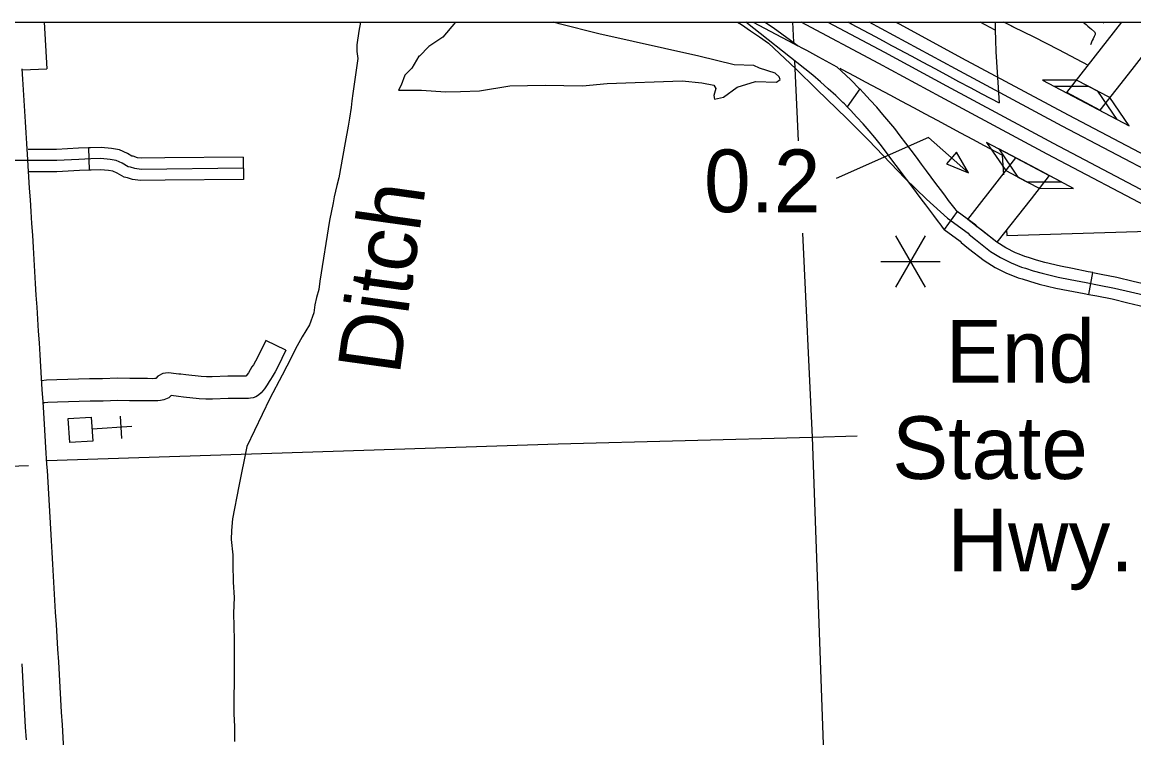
# Model space of a CAD drawing. Extents: x -117616 to 64730, y 54117 to 789866.
# Drawn here: x 62435.1 to 62585, y 55218.5 to 55314.9 of the extents above; entities that cross this region are included whole.
import ezdxf

# ---------------------------------------------------------------- set-up
doc = ezdxf.new("R2010")
doc.units = 0
for name, color, linetype in [('Level 10', 7, 'Continuous'), ('Level 19', 7, 'Continuous'), ('Level 31', 7, 'Continuous'), ('Level 32', 7, 'Continuous'), ('Level 33', 7, 'Continuous'), ('Level 34', 7, 'Continuous'), ('Level 35', 7, 'Continuous'), ('Level 40', 7, 'Continuous'), ('Level 41', 7, 'Continuous'), ('Level 42', 7, 'Continuous'), ('Level 45', 7, 'Continuous'), ('Level 46', 7, 'Continuous'), ('Level 48', 7, 'Continuous'), ('Level 5', 7, 'Continuous'), ('Level 57', 7, 'Continuous'), ('Level 6', 7, 'Continuous'), ('R_No Plot', 7, 'Continuous')]:
    doc.layers.add(name, color=color, linetype=linetype)

msp = doc.modelspace()

# ---------------------------------------------------------------- linework, layer by layer
at = {"layer": 'Level 10'}
for p, q in [((62575.96, 55305.45), (62583.37, 55314.94)), ((62583.37, 55314.94), (62589.63, 55314.94)), ((62588.03, 55312.78), (62584.75, 55308.58)), ((62435.19, 55307.25), (62435.11, 55308.67)), ((62584.75, 55308.58), (62580.44, 55303.07)), ((62435.28, 55305.83), (62435.19, 55307.25)), ((62435.37, 55304.39), (62435.28, 55305.83)), ((62580.44, 55303.07), (62575.96, 55305.45)), ((62435.46, 55302.95), (62435.37, 55304.39)), ((62435.56, 55301.5), (62435.46, 55302.95)), ((62435.65, 55300.04), (62435.56, 55301.5)), ((62435.74, 55298.58), (62435.65, 55300.04)), ((62435.83, 55297.1), (62435.74, 55298.58)), ((62435.87, 55296.44), (62435.83, 55297.1)), ((62435.92, 55295.6), (62435.87, 55296.44)), ((62436, 55294.09), (62435.92, 55295.6)), ((62436.1, 55292.57), (62436, 55294.09)), ((62436.21, 55291.01), (62436.1, 55292.57)), ((62436.31, 55289.42), (62436.21, 55291.01)), ((62436.42, 55287.82), (62436.31, 55289.42)), ((62436.52, 55286.21), (62436.42, 55287.82)), ((62436.62, 55284.58), (62436.52, 55286.21)), ((62436.71, 55282.97), (62436.62, 55284.58)), ((62436.81, 55281.34), (62436.71, 55282.97)), ((62436.91, 55279.73), (62436.81, 55281.34)), ((62437, 55278.12), (62436.91, 55279.73)), ((62437.11, 55276.52), (62437, 55278.12)), ((62437.21, 55274.91), (62437.11, 55276.52)), ((62437.32, 55273.31), (62437.21, 55274.91)), ((62437.42, 55271.71), (62437.32, 55273.31)), ((62437.52, 55270.12), (62437.42, 55271.71)), ((62437.62, 55268.54), (62437.52, 55270.12)), ((62437.72, 55266.97), (62437.62, 55268.54)), ((62437.82, 55265.42), (62437.72, 55266.97)), ((62437.93, 55263.74), (62437.82, 55265.42)), ((62438.02, 55262.3), (62437.93, 55263.74)), ((62438.12, 55260.74), (62438.02, 55262.3)), ((62438.22, 55259.18), (62438.12, 55260.74)), ((62438.31, 55257.62), (62438.22, 55259.18)), ((62438.45, 55255.34), (62438.31, 55257.62)), ((62438.5, 55254.5), (62438.45, 55255.34)), ((62438.6, 55252.94), (62438.5, 55254.5)), ((62438.69, 55251.37), (62438.6, 55252.94)), ((62438.79, 55249.8), (62438.69, 55251.37)), ((62438.88, 55248.23), (62438.79, 55249.8)), ((62438.97, 55246.65), (62438.88, 55248.23)), ((62439.06, 55245.06), (62438.97, 55246.65)), ((62439.16, 55243.47), (62439.06, 55245.06)), ((62439.25, 55241.87), (62439.16, 55243.47)), ((62439.35, 55240.26), (62439.25, 55241.87)), ((62439.44, 55238.65), (62439.35, 55240.26)), ((62439.53, 55237.03), (62439.44, 55238.65)), ((62439.62, 55235.41), (62439.53, 55237.03)), ((62439.72, 55233.76), (62439.62, 55235.41)), ((62439.82, 55232.1), (62439.72, 55233.76)), ((62439.93, 55230.42), (62439.82, 55232.1)), ((62440.03, 55228.72), (62439.93, 55230.42)), ((62440.13, 55227.01), (62440.03, 55228.72)), ((62435.04, 55228.42), (62435.13, 55226.73)), ((62435.13, 55226.73), (62435.23, 55225.03)), ((62440.22, 55225.31), (62440.13, 55227.01)), ((62435.23, 55225.03), (62435.33, 55223.33)), ((62440.32, 55223.62), (62440.22, 55225.31)), ((62435.33, 55223.33), (62435.43, 55221.62)), ((62440.42, 55221.92), (62440.32, 55223.62)), ((62435.43, 55221.62), (62435.53, 55219.91)), ((62440.53, 55220.22), (62440.42, 55221.92)), ((62435.53, 55219.91), (62435.64, 55218.21)), ((62440.63, 55218.52), (62440.53, 55220.22)), ((62440.74, 55216.81), (62440.63, 55218.52))]:
    msp.add_line(p, q, dxfattribs=at)
for points in [[(62566.54, 55285.27), (62562.6, 55288.35), (62567.21, 55294.23), (62569.09, 55296.64), (62573.57, 55294.26)], [(62573.57, 55294.26), (62571.15, 55291.15), (62566.54, 55285.27)]]:
    msp.add_lwpolyline(points, dxfattribs=at)
at = {"layer": 'Level 19'}
for p, q in [((62550.6, 55309.38), (62540.14, 55314.94)), ((62540.14, 55314.94), (62543.76, 55314.94)), ((62543.76, 55314.94), (62551.4, 55310.88)), ((62552.63, 55313.17), (62549.3, 55314.94)), ((62549.3, 55314.94), (62552.93, 55314.94)), ((62552.93, 55314.94), (62553.44, 55314.67)), ((62553.44, 55314.67), (62561.78, 55310.14)), ((62560.98, 55308.64), (62552.63, 55313.17)), ((62551.4, 55310.88), (62559.74, 55306.35)), ((62561.78, 55310.14), (62576.16, 55302.44)), ((62558.94, 55304.86), (62550.6, 55309.38)), ((62575.36, 55300.93), (62560.98, 55308.64)), ((62559.74, 55306.35), (62574.14, 55298.64)), ((62573.34, 55297.14), (62558.94, 55304.86)), ((62576.16, 55302.44), (62594.33, 55292.86)), ((62593.52, 55291.37), (62575.36, 55300.93)), ((62574.14, 55298.64), (62592.28, 55289.08)), ((62591.47, 55287.59), (62573.34, 55297.14))]:
    msp.add_line(p, q, dxfattribs=at)
at = {"layer": 'Level 31'}
for p, q in [((62540.62, 55308.67), (62532.69, 55314.94)), ((62532.69, 55314.94), (62533.69, 55314.94)), ((62533.69, 55314.94), (62535.99, 55313.74)), ((62566.33, 55313.89), (62564.3, 55314.94)), ((62564.3, 55314.94), (62566.3, 55314.94)), ((62566.3, 55314.94), (62566.33, 55313.89)), ((62535.99, 55313.74), (62539.11, 55312.08)), ((62539.11, 55312.08), (62540.87, 55311.15)), ((62540.87, 55311.15), (62542.48, 55310.28)), ((62542.48, 55310.28), (62544.97, 55308.94)), ((62541.71, 55307.79), (62540.62, 55308.67)), ((62544.97, 55308.94), (62546.84, 55307.16)), ((62542.77, 55306.89), (62541.71, 55307.79)), ((62543.8, 55305.98), (62542.77, 55306.89)), ((62546.84, 55307.16), (62547.05, 55306.95)), ((62547.05, 55306.95), (62547.81, 55306.2)), ((62544.81, 55305.06), (62543.8, 55305.98)), ((62545.78, 55304.13), (62544.81, 55305.06)), ((62548.05, 55305.95), (62546.35, 55303.55)), ((62547.81, 55306.2), (62547.93, 55306.07)), ((62547.93, 55306.07), (62548.05, 55305.95)), ((62545.98, 55303.95), (62545.78, 55304.13)), ((62546.35, 55303.55), (62545.98, 55303.95)), ((62561.2, 55289.42), (62559.43, 55287.01)), ((62578.93, 55278.24), (62579.49, 55281.19)), ((62578.93, 55278.24), (62578.93, 55278.24))]:
    msp.add_line(p, q, dxfattribs=at)
for points in [[(62531.58, 55314.94), (62532.11, 55314.61), (62533.33, 55313.8), (62534.54, 55312.97), (62535.73, 55312.11)], [(62567.58, 55314.94), (62568.73, 55314.34), (62571.52, 55312.97), (62574.84, 55311.28), (62578.83, 55309.13)], [(62535.73, 55312.11), (62539.44, 55308.67), (62542.28, 55305.89), (62546.29, 55301.95), (62549.22, 55299.02), (62554.17, 55293.87), (62557.04, 55291.07), (62559.9, 55288.52), (62562.66, 55286.49), (62562.8, 55286.31), (62563.65, 55285.63)], [(62561.2, 55289.42), (62560.92, 55289.76), (62560.54, 55290.24), (62560.03, 55290.92), (62559.5, 55291.64), (62558.93, 55292.4), (62558.32, 55293.21), (62557.7, 55294.04), (62557.04, 55294.91), (62556.37, 55295.8), (62555.68, 55296.73), (62554.97, 55297.68), (62554.25, 55298.65), (62553.51, 55299.62), (62552.76, 55300.59), (62551.99, 55301.56), (62551.18, 55302.52), (62550.33, 55303.48), (62549.46, 55304.44), (62548.57, 55305.41), (62548.05, 55305.95)], [(62559.43, 55287.01), (62559.01, 55287.57), (62558.54, 55288.19), (62558.04, 55288.87), (62557.51, 55289.59), (62556.94, 55290.34), (62556.34, 55291.14), (62555.71, 55291.98), (62555.06, 55292.85), (62554.37, 55293.76), (62553.69, 55294.68), (62552.98, 55295.63), (62552.26, 55296.58), (62551.54, 55297.54), (62550.82, 55298.48), (62550.08, 55299.4), (62549.31, 55300.31), (62548.51, 55301.23), (62547.66, 55302.16), (62546.8, 55303.09), (62546.35, 55303.55)], [(62569.54, 55283.67), (62569.07, 55283.86), (62567.75, 55284.52), (62566.54, 55285.27), (62564.58, 55286.8), (62563.88, 55287.36), (62563.72, 55287.57), (62561.2, 55289.42)], [(62559.43, 55287.01), (62561.6, 55285.41), (62561.72, 55285.25), (62562.71, 55284.45), (62564.82, 55282.8), (62566.29, 55281.89), (62567.84, 55281.12), (62568.43, 55280.89)], [(62563.65, 55285.63), (62565.68, 55284.03), (62567.02, 55283.21), (62568.46, 55282.49), (62569.85, 55281.93), (62570.39, 55281.8), (62571.41, 55281.44), (62572.64, 55281.09), (62574.82, 55280.56), (62576.44, 55280.24), (62578.58, 55279.83), (62580.31, 55279.5), (62582.42, 55279.1), (62584.55, 55278.59), (62586.89, 55278.04)], [(62579.49, 55281.19), (62578.86, 55281.31), (62576.72, 55281.72), (62575.14, 55282.03), (62573.02, 55282.54), (62571.87, 55282.87), (62570.82, 55283.24), (62570.31, 55283.36), (62569.54, 55283.67)], [(62579.49, 55281.19), (62580.59, 55280.98), (62582.73, 55280.56), (62584.9, 55280.05), (62587.26, 55279.49), (62589.64, 55278.83), (62589.89, 55278.76)], [(62568.43, 55280.89), (62569.39, 55280.5), (62569.97, 55280.36), (62570.96, 55280.01), (62572.26, 55279.64), (62574.5, 55279.1), (62576.15, 55278.77), (62578.3, 55278.36), (62578.93, 55278.24)], [(62578.93, 55278.24), (62580.03, 55278.03), (62582.1, 55277.63), (62584.2, 55277.13), (62586.51, 55276.59), (62588.84, 55275.95), (62589.08, 55275.88)]]:
    msp.add_lwpolyline(points, dxfattribs=at)
at = {"layer": 'Level 32'}
msp.add_lwpolyline([(62406.52, 55254.14), (62409.69, 55254.26), (62435.95, 55255.19)], dxfattribs=at)
at = {"layer": 'Level 33'}
for points in [[(62539.6, 55311.82), (62538.73, 55312.47), (62537.55, 55313.33), (62536.36, 55314.17), (62535.22, 55314.94)], [(62568.73, 55314.34), (62567.76, 55314.8), (62567.46, 55314.94)]]:
    msp.add_lwpolyline(points, dxfattribs=at)
at = {"layer": 'Level 34'}
msp.add_lwpolyline([(62578.19, 55314.94), (62578.59, 55314.64), (62578.82, 55314.4), (62579.06, 55314.17), (62579.3, 55313.99), (62579.7, 55313.63), (62579.75, 55313.57), (62579.79, 55313.51), (62579.8, 55313.4), (62579.78, 55313.28), (62579.68, 55313.02), (62579.51, 55312.69), (62579.37, 55312.48), (62579.15, 55311.91)], dxfattribs=at)
at = {"layer": 'Level 35'}
for points in [[(62480.72, 55314.94), (62480.49, 55313.75), (62480.24, 55311.87), (62480.24, 55311.01), (62480.37, 55310.07), (62479.71, 55305.35), (62479.54, 55304.33), (62479.45, 55303.43), (62479.23, 55302), (62479.07, 55300.91), (62478.67, 55298.72), (62478.35, 55296.99), (62477.79, 55293.97), (62477.54, 55292.93), (62477.19, 55291.39), (62477.03, 55290.6), (62476.53, 55288.21), (62475.24, 55280.01), (62475.12, 55278.91), (62474.8, 55277.84), (62474.58, 55276.83), (62474.43, 55275.76), (62473.86, 55274.13), (62472.84, 55272.53), (62472.2, 55271.29), (62470.81, 55268.56), (62470.15, 55267.37), (62468.52, 55264.22), (62465.41, 55257.73), (62464.32, 55252.41), (62463.48, 55247.99), (62463.33, 55246.43), (62463.29, 55245.21), (62463.52, 55243.12), (62463.52, 55241.89), (62463.56, 55239.44), (62463.68, 55237.39), (62463.6, 55235.28), (62463.68, 55231.67), (62463.68, 55228.68), (62463.69, 55227.51), (62463.68, 55225.43), (62463.64, 55224.5), (62463.65, 55223.28), (62463.64, 55221.72), (62463.72, 55220), (62463.73, 55217.97)], [(62493.54, 55314.94), (62491.83, 55312.93), (62489.96, 55311.65), (62488.68, 55310.37), (62488.59, 55310.37), (62487.65, 55308.75), (62486.72, 55307.81), (62486.21, 55306.45), (62485.87, 55305.77), (62488.93, 55305.77), (62492.18, 55305.54), (62494.22, 55305.6), (62496.77, 55305.68), (62500.86, 55306.36), (62505.63, 55306.45), (62510.66, 55306.36), (62513.98, 55306.7), (62524.12, 55307.04), (62526.76, 55306.79), (62528.38, 55306.45), (62528.64, 55306.02), (62528.38, 55305.08), (62528.47, 55304.57), (62529.66, 55304.83), (62531.53, 55306.19), (62534, 55306.96), (62536.82, 55306.87), (62537.33, 55307.22), (62537.16, 55307.56), (62536.65, 55308.07), (62534.52, 55308.75), (62533.75, 55309.09), (62531.11, 55309.18), (62526.34, 55310.37), (62512.87, 55313.36), (62507.51, 55314.72), (62506.8, 55314.94)]]:
    msp.add_lwpolyline(points, dxfattribs=at)
at = {"layer": 'Level 40'}
msp.add_line((62580.92, 55314.94), (62580.82, 55314.79), dxfattribs=at)
at = {"layer": 'Level 42'}
for p, q in [((62577.28, 55307.14), (62572.67, 55307.13)), ((62572.67, 55307.13), (62577.71, 55304.48)), ((62580.15, 55305.63), (62577.28, 55307.14)), ((62578.91, 55306.29), (62574.29, 55306.28)), ((62574.29, 55306.28), (62579.34, 55303.62)), ((62581.78, 55304.78), (62578.91, 55306.29)), ((62582.76, 55301.82), (62580.15, 55305.63)), ((62577.71, 55304.48), (62582.76, 55301.82)), ((62579.34, 55303.62), (62584.38, 55300.96)), ((62584.38, 55300.96), (62581.78, 55304.78)), ((62570.19, 55296.08), (62565.16, 55298.74)), ((62565.16, 55298.74), (62567.75, 55294.93)), ((62571.82, 55295.21), (62566.79, 55297.88)), ((62566.79, 55297.88), (62569.38, 55294.06)), ((62575.23, 55293.41), (62570.19, 55296.08)), ((62567.75, 55294.93), (62570.62, 55293.41)), ((62576.86, 55292.54), (62571.82, 55295.21)), ((62569.38, 55294.06), (62572.25, 55292.55)), ((62570.62, 55293.41), (62575.23, 55293.41)), ((62572.25, 55292.55), (62576.86, 55292.54))]:
    msp.add_line(p, q, dxfattribs=at)
at = {"layer": 'Level 45'}
for p, q in [((62444.03, 55297.99), (62444.13, 55294.99)), ((62464.91, 55296.75), (62464.95, 55293.75))]:
    msp.add_line(p, q, dxfattribs=at)
for points in [[(62444.03, 55297.99), (62442.7, 55297.94), (62439.72, 55297.79), (62437.44, 55297.79), (62435.92, 55297.79)], [(62454.36, 55296.64), (62451.22, 55296.6), (62450.64, 55296.67), (62450.05, 55296.87), (62449.9, 55296.89), (62449.29, 55297.26), (62448.22, 55297.73), (62447.15, 55297.93), (62445.74, 55298.05), (62444.31, 55298), (62444.03, 55297.99)], [(62464.93, 55295.25), (62451.13, 55295.1), (62450.31, 55295.2), (62449.69, 55295.41), (62449.38, 55295.46), (62448.6, 55295.93), (62447.77, 55296.29), (62446.95, 55296.44), (62445.71, 55296.55), (62444.36, 55296.5), (62442.76, 55296.44), (62439.76, 55296.29), (62437.44, 55296.29), (62433.37, 55296.29)], [(62464.91, 55296.75), (62454.36, 55296.64)], [(62444.13, 55294.99), (62442.82, 55294.95), (62439.8, 55294.79), (62437.44, 55294.79), (62435.92, 55294.79)], [(62454.39, 55293.64), (62451.05, 55293.6), (62449.97, 55293.73), (62449.32, 55293.95), (62448.85, 55294.03), (62447.91, 55294.59), (62447.33, 55294.85), (62446.75, 55294.96), (62445.67, 55295.05), (62444.42, 55295), (62444.13, 55294.99)], [(62464.95, 55293.75), (62454.39, 55293.64)]]:
    msp.add_lwpolyline(points, dxfattribs=at)
at = {"layer": 'Level 46'}
for points in [[(62470.64, 55270.73), (62467.94, 55272.03), (62466.88, 55269.82), (62466.57, 55269.23), (62466.29, 55268.75), (62466.09, 55268.46), (62465.84, 55268.08), (62465.61, 55267.68), (62465.33, 55267.28), (62465.27, 55267.21), (62465.13, 55267.22), (62464.48, 55267.23), (62462.83, 55267.23), (62460.71, 55267.13), (62459.96, 55267.13), (62459.22, 55267.17), (62457.19, 55267.39), (62456.52, 55267.47), (62456.22, 55267.5), (62455.88, 55267.54), (62455.49, 55267.59), (62455.19, 55267.63), (62454.78, 55267.65), (62454.07, 55267.58), (62453.4, 55267.22), (62453.15, 55266.9), (62453.12, 55266.9), (62452.98, 55266.89), (62452.62, 55266.88), (62452.02, 55266.89), (62449.6, 55266.9), (62447.99, 55266.95), (62445.89, 55266.86)], [(62470.64, 55270.73), (62469.56, 55268.48), (62469.2, 55267.79), (62468.82, 55267.13), (62468.57, 55266.77), (62468.4, 55266.51), (62468.13, 55266.06), (62467.76, 55265.52), (62467.35, 55264.98), (62466.98, 55264.68), (62466.63, 55264.45), (62466.24, 55264.31), (62465.91, 55264.24), (62465.64, 55264.22), (62465.37, 55264.21), (62465.06, 55264.22), (62464.46, 55264.23), (62462.9, 55264.23), (62460.79, 55264.13), (62459.87, 55264.13), (62458.97, 55264.18), (62456.86, 55264.41), (62456.19, 55264.48), (62455.87, 55264.52), (62455.5, 55264.57), (62455.2, 55264.6), (62454.86, 55264.29), (62454.2, 55264.05), (62453.75, 55263.96), (62453.41, 55263.91), (62453.08, 55263.89), (62452.63, 55263.88), (62451.99, 55263.89), (62449.56, 55263.9), (62448.01, 55263.94), (62446.01, 55263.87)], [(62445.93, 55266.87), (62444.2, 55266.85), (62439.79, 55266.71), (62438.38, 55266.67), (62437.69, 55266.6)], [(62445.97, 55263.87), (62444.27, 55263.85), (62439.89, 55263.72), (62438.58, 55263.67), (62438.05, 55263.62), (62437.89, 55263.51)]]:
    msp.add_lwpolyline(points, dxfattribs=at)
at = {"layer": 'Level 48'}
for p, q in [((62556.87, 55286.15), (62552.87, 55279.22)), ((62552.87, 55286.15), (62556.87, 55279.22)), ((62550.87, 55282.68), (62558.87, 55282.68))]:
    msp.add_line(p, q, dxfattribs=at)
msp.add_lwpolyline([(62562.71, 55294.62), (62557.34, 55299.42), (62544.88, 55293.85)], dxfattribs=at)
msp.add_lwpolyline([(62561.08, 55297.4), (62559.74, 55295.87), (62562.71, 55294.62)], close=True, dxfattribs=at)
at = {"layer": 'Level 5'}
for points in [[(62538.97, 55314.94), (62539.1, 55312.23)], [(62539.23, 55309.69), (62539.74, 55298.97)], [(62540.33, 55286.48), (62541.65, 55258.99)], [(62438.42, 55255.83), (62507.38, 55258.1), (62541.65, 55258.99)], [(62541.65, 55258.99), (62547.68, 55259.17)], [(62541.65, 55258.99), (62543.14, 55216.35)]]:
    msp.add_lwpolyline(points, dxfattribs=at)
at = {"layer": 'Level 57'}
for p, q in [((62448.32, 55261.83), (62448.51, 55258.84)), ((62449.91, 55260.43), (62444.54, 55260.09))]:
    msp.add_line(p, q, dxfattribs=at)
msp.add_lwpolyline([(62441.32, 55261.51), (62444.43, 55261.71), (62444.64, 55258.48), (62441.53, 55258.28)], close=True, dxfattribs=at)
at = {"layer": 'Level 6'}
for points in [[(62438.08, 55314.94), (62438.41, 55308.65)], [(62551.73, 55312.12), (62550.16, 55312.96), (62548.55, 55313.82), (62546.93, 55314.69), (62546.49, 55314.94)], [(62566.33, 55313.89), (62566.37, 55312.56)], [(62566.37, 55312.56), (62566.42, 55310.93), (62566.83, 55304.05)], [(62539.11, 55312.08), (62539.72, 55311.76)], [(62551.73, 55312.12), (62553.36, 55311.24), (62554.96, 55310.39), (62556.56, 55309.54), (62558.16, 55308.68), (62559.75, 55307.83), (62561.35, 55306.97), (62562.94, 55306.12), (62564.53, 55305.27), (62566.83, 55304.05)], [(62435.12, 55308.54), (62438.41, 55308.65)], [(62567.25, 55297.02), (62564.88, 55298.29), (62563.3, 55299.13), (62561.7, 55299.98), (62560.11, 55300.83), (62558.52, 55301.68), (62556.92, 55302.54), (62555.32, 55303.4), (62553.73, 55304.25), (62552.14, 55305.1), (62550.54, 55305.95), (62548.93, 55306.81), (62547.32, 55307.67), (62545.7, 55308.54), (62545.41, 55308.7)], [(62567.25, 55297.02), (62567.41, 55294.37)], [(62567.89, 55286.19), (62594.29, 55286.98)], [(62567.85, 55286.97), (62567.89, 55286.19)]]:
    msp.add_lwpolyline(points, dxfattribs=at)
at = {"layer": 'R_No Plot'}
msp.add_lwpolyline([(62347.42, 55314.94), (63854.85, 55314.94), (63854.85, 54389.3), (62347.42, 54389.3)], close=True, dxfattribs=at)

# ---------------------------------------------------------------- texts
at = {"layer": 'Level 35'}
msp.add_text('Ditch', height=8.448, rotation=82.0736, dxfattribs=at).set_placement((62485.98, 55267.24))
at = {"layer": 'Level 41'}
for s, p in [('End', (62559.67, 55266.36)), ('State', (62552.43, 55253.36)), ('Hwy.', (62559.88, 55240.91))]:
    msp.add_text(s, height=8.448, dxfattribs=at).set_placement(p)
at = {"layer": 'Level 48'}
msp.add_text('0.2', height=8.448, dxfattribs=at).set_placement((62527.05, 55289.33))

doc.saveas('drawing.dxf')
